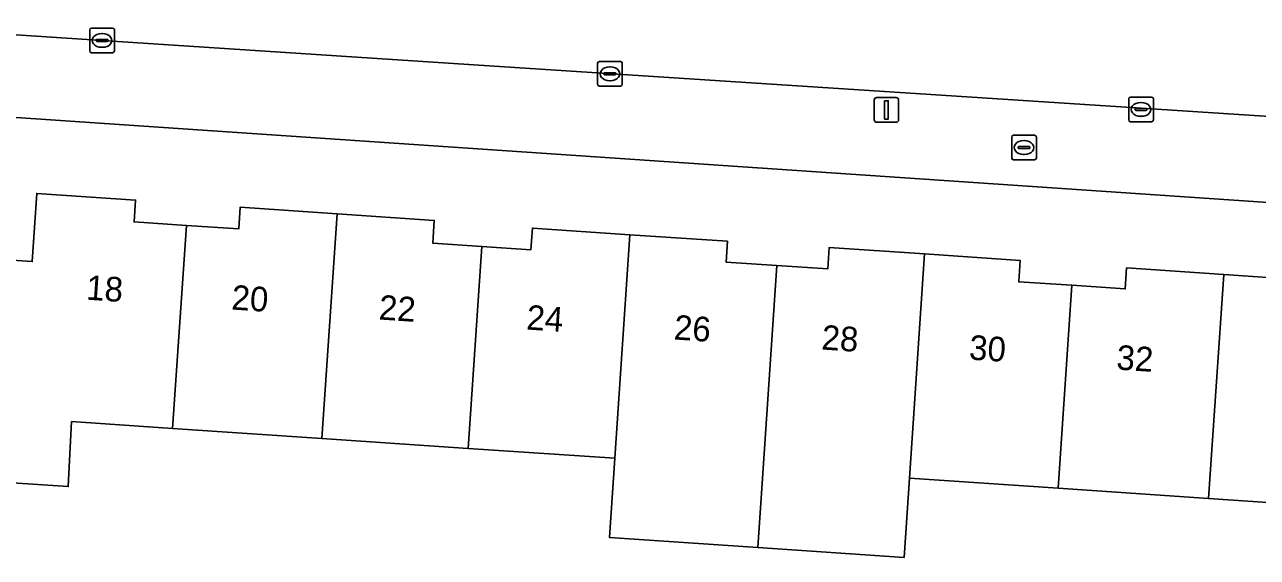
# Model space of a CAD drawing. Extents: x 161848 to 162726, y 385382 to 386521.
# Drawn here: x 162339.2 to 162389.2, y 385439.2 to 385460.8 of the extents above; entities that cross this region are included whole.
import ezdxf

# ---------------------------------------------------------------- set-up
doc = ezdxf.new("R2010")
doc.units = 0
for name, color, linetype in [('IMGEO_Brandkraan', 7, 'Continuous'), ('IMGEO_Erf', 7, 'Continuous'), ('IMGEO_Kolk', 7, 'Continuous'), ('IMGEO_Lichtmast', 7, 'Continuous'), ('IMGEO_Pand', 7, 'Continuous'), ('IMGEO_Pand_nummerreeks', 7, 'Continuous'), ('IMGEO_Rijbaan_lokaal_open', 7, 'Continuous'), ('IMGEO_Voetpad_open', 7, 'Continuous')]:
    doc.layers.add(name, color=color, linetype=linetype)

msp = doc.modelspace()

# ---------------------------------------------------------------- linework, layer by layer
at = {"layer": 'IMGEO_Brandkraan'}
for p, q in [((162379.246, 385455.432), (162379.246, 385456.284)), ((162379.321, 385456.358), (162380.173, 385456.358)), ((162379.734, 385456.138), (162379.759, 385456.138)), ((162380.247, 385456.284), (162380.247, 385455.432)), ((162379.505, 385455.852), (162379.505, 385455.864)), ((162379.943, 385455.815), (162379.545, 385455.815)), ((162379.548, 385455.901), (162379.946, 385455.901)), ((162379.757, 385455.578), (162379.732, 385455.578)), ((162379.989, 385455.864), (162379.989, 385455.852)), ((162380.173, 385455.358), (162379.321, 385455.358))]:
    msp.add_line(p, q, dxfattribs=at)
for points in [[(162379.246, 385455.432), (162379.246, 385456.284)], [(162379.321, 385456.358), (162380.173, 385456.358)], [(162380.247, 385456.284), (162380.247, 385455.432)], [(162380.173, 385455.358), (162379.321, 385455.358)]]:
    msp.add_lwpolyline(points, dxfattribs=at)
for centre, radius, start, end in [((162379.323, 385456.282), 0.0765, 91.552, 178.448), ((162379.323, 385456.282), 0.0765, 91.552, 178.448), ((162380.171, 385456.282), 0.0765, 1.552, 88.448), ((162380.171, 385456.282), 0.0765, 1.552, 88.448), ((162379.545, 385455.861), 0.0403, 85.8775, 175.7526), ((162379.542, 385455.851), 0.0366, 178.938, 274.7102), ((162379.946, 385455.858), 0.043, 264.8664, 352.4533), ((162379.95, 385455.863), 0.0386, 1.7309, 96.639), ((162379.323, 385455.434), 0.0765, 181.552, 268.448), ((162379.323, 385455.434), 0.0765, 181.552, 268.448), ((162380.171, 385455.434), 0.0765, 271.552, 358.448), ((162380.171, 385455.434), 0.0765, 271.552, 358.448)]:
    msp.add_arc(centre, radius, start, end, dxfattribs=at)
for centre, major_axis, ratio, start_param, end_param in [((162379.733, 385455.858), (-0.387, 0.002), 0.722429, 4.712389, 7.853982), ((162379.758, 385455.858), (-0.39, 0.002), 0.717154, 1.570796, 4.712389)]:
    msp.add_ellipse(centre, major_axis=major_axis, ratio=ratio, start_param=start_param, end_param=end_param, dxfattribs=at)
at = {"layer": 'IMGEO_Erf'}
for points in [[(162428.108, 385451.016), (162424.152, 385451.285), (162286.568, 385460.627), (162285.504, 385460.702)], [(162336.992, 385451.392), (162339.469, 385451.225), (162339.657, 385453.996), (162343.668, 385453.725), (162343.608, 385452.839), (162345.731, 385452.695), (162347.854, 385452.552), (162347.913, 385453.433), (162351.854, 385453.167), (162355.796, 385452.9), (162355.734, 385451.978), (162357.73, 385451.843), (162359.725, 385451.708), (162359.785, 385452.588), (162363.745, 385452.32), (162367.703, 385452.053), (162367.646, 385451.21), (162369.71, 385451.07), (162371.773, 385450.931), (162371.831, 385451.798), (162375.71, 385451.536), (162379.59, 385451.274), (162379.532, 385450.412), (162381.692, 385450.266), (162383.856, 385450.119), (162383.913, 385450.971), (162387.858, 385450.704), (162391.799, 385450.438)], [(162393.234, 385441.208), (162387.24, 385441.613), (162381.132, 385442.026), (162375.092, 385442.434), (162374.874, 385439.222), (162368.933, 385439.625), (162362.911, 385440.033), (162363.129, 385443.242), (162357.173, 385443.645), (162351.235, 385444.046), (162345.172, 385444.456), (162341.069, 385444.732), (162340.934, 385442.094), (162336.396, 385442.4)]]:
    msp.add_lwpolyline(points, dxfattribs=at)
at = {"layer": 'IMGEO_Kolk'}
for p, q in [((162341.805, 385459.78), (162341.805, 385460.632)), ((162341.88, 385460.706), (162342.732, 385460.706)), ((162342.293, 385460.486), (162342.318, 385460.486)), ((162342.806, 385460.632), (162342.806, 385459.78)), ((162342.064, 385460.2), (162342.064, 385460.212)), ((162342.502, 385460.163), (162342.104, 385460.163)), ((162342.107, 385460.249), (162342.505, 385460.249)), ((162342.548, 385460.212), (162342.548, 385460.2)), ((162342.732, 385459.706), (162341.88, 385459.706)), ((162342.316, 385459.926), (162342.291, 385459.926)), ((162362.43, 385458.424), (162362.43, 385459.276)), ((162362.505, 385459.35), (162363.357, 385459.35)), ((162362.918, 385459.13), (162362.943, 385459.13)), ((162363.431, 385459.276), (162363.431, 385458.424)), ((162362.689, 385458.844), (162362.689, 385458.856)), ((162363.127, 385458.807), (162362.729, 385458.807)), ((162362.732, 385458.893), (162363.13, 385458.893)), ((162362.941, 385458.57), (162362.916, 385458.57)), ((162363.173, 385458.856), (162363.173, 385458.844)), ((162363.357, 385458.35), (162362.505, 385458.35)), ((162383.997, 385456.978), (162383.997, 385457.83)), ((162384.072, 385457.904), (162384.924, 385457.904)), ((162384.485, 385457.684), (162384.51, 385457.684)), ((162384.998, 385457.83), (162384.998, 385456.978)), ((162384.256, 385457.398), (162384.256, 385457.41)), ((162384.694, 385457.361), (162384.296, 385457.361)), ((162384.299, 385457.447), (162384.697, 385457.447)), ((162384.508, 385457.124), (162384.483, 385457.124)), ((162384.74, 385457.41), (162384.74, 385457.398)), ((162384.924, 385456.904), (162384.072, 385456.904))]:
    msp.add_line(p, q, dxfattribs=at)
for points in [[(162341.805, 385459.78), (162341.805, 385460.632)], [(162341.88, 385460.706), (162342.732, 385460.706)], [(162342.806, 385460.632), (162342.806, 385459.78)], [(162342.732, 385459.706), (162341.88, 385459.706)], [(162362.43, 385458.424), (162362.43, 385459.276)], [(162362.505, 385459.35), (162363.357, 385459.35)], [(162363.431, 385459.276), (162363.431, 385458.424)], [(162363.357, 385458.35), (162362.505, 385458.35)], [(162383.997, 385456.978), (162383.997, 385457.83)], [(162384.072, 385457.904), (162384.924, 385457.904)], [(162384.998, 385457.83), (162384.998, 385456.978)], [(162384.924, 385456.904), (162384.072, 385456.904)]]:
    msp.add_lwpolyline(points, dxfattribs=at)
for centre, radius, start, end in [((162341.882, 385460.63), 0.0765, 91.552, 178.448), ((162341.882, 385460.63), 0.0765, 91.552, 178.448), ((162342.73, 385460.63), 0.0765, 1.552, 88.448), ((162342.73, 385460.63), 0.0765, 1.552, 88.448), ((162342.104, 385460.209), 0.0403, 85.8775, 175.7526), ((162342.101, 385460.199), 0.0366, 178.938, 274.7102), ((162342.505, 385460.206), 0.043, 264.8664, 352.4533), ((162342.509, 385460.211), 0.0386, 1.7309, 96.639), ((162341.882, 385459.782), 0.0765, 181.552, 268.448), ((162341.882, 385459.782), 0.0765, 181.552, 268.448), ((162342.73, 385459.782), 0.0765, 271.552, 358.448), ((162342.73, 385459.782), 0.0765, 271.552, 358.448), ((162362.507, 385459.274), 0.0765, 91.552, 178.448), ((162362.507, 385459.274), 0.0765, 91.552, 178.448), ((162363.355, 385459.274), 0.0765, 1.552, 88.448), ((162363.355, 385459.274), 0.0765, 1.552, 88.448), ((162362.729, 385458.853), 0.0403, 85.8775, 175.7526), ((162362.726, 385458.843), 0.0366, 178.938, 274.7102), ((162363.13, 385458.85), 0.043, 264.8664, 352.4533), ((162363.134, 385458.855), 0.0386, 1.7309, 96.639), ((162362.507, 385458.426), 0.0765, 181.552, 268.448), ((162362.507, 385458.426), 0.0765, 181.552, 268.448), ((162363.355, 385458.426), 0.0765, 271.552, 358.448), ((162363.355, 385458.426), 0.0765, 271.552, 358.448), ((162384.074, 385457.828), 0.0765, 91.552, 178.448), ((162384.074, 385457.828), 0.0765, 91.552, 178.448), ((162384.922, 385457.828), 0.0765, 1.552, 88.448), ((162384.922, 385457.828), 0.0765, 1.552, 88.448), ((162384.074, 385456.98), 0.0765, 181.552, 268.448), ((162384.074, 385456.98), 0.0765, 181.552, 268.448), ((162384.296, 385457.407), 0.0403, 85.8775, 175.7526), ((162384.293, 385457.397), 0.0366, 178.938, 274.7102), ((162384.697, 385457.404), 0.043, 264.8664, 352.4533), ((162384.701, 385457.409), 0.0386, 1.7309, 96.639), ((162384.922, 385456.98), 0.0765, 271.552, 358.448), ((162384.922, 385456.98), 0.0765, 271.552, 358.448)]:
    msp.add_arc(centre, radius, start, end, dxfattribs=at)
for centre, major_axis, ratio, start_param, end_param in [((162342.292, 385460.206), (-0.387, 0.002), 0.722429, 4.712389, 7.853982), ((162342.317, 385460.206), (-0.39, 0.002), 0.717154, 1.570796, 4.712389), ((162362.917, 385458.85), (-0.387, 0.002), 0.722429, 4.712389, 7.853982), ((162362.942, 385458.85), (-0.39, 0.002), 0.717154, 1.570796, 4.712389), ((162384.484, 385457.404), (-0.387, 0.002), 0.722429, 4.712389, 7.853982), ((162384.509, 385457.404), (-0.39, 0.002), 0.717154, 1.570796, 4.712389)]:
    msp.add_ellipse(centre, major_axis=major_axis, ratio=ratio, start_param=start_param, end_param=end_param, dxfattribs=at)
at = {"layer": 'IMGEO_Lichtmast'}
for p, q in [((162373.661, 385456.985), (162373.661, 385457.785)), ((162373.661, 385457.785), (162373.661, 385456.985)), ((162373.761, 385457.885), (162374.551, 385457.885)), ((162374.551, 385457.885), (162373.761, 385457.885)), ((162374.651, 385457.785), (162374.651, 385456.985)), ((162374.651, 385456.985), (162374.651, 385457.785)), ((162374.551, 385456.885), (162373.761, 385456.885)), ((162373.761, 385456.885), (162374.551, 385456.885))]:
    msp.add_line(p, q, dxfattribs=at)
msp.add_lwpolyline([(162374.081, 385457.76), (162374.231, 385457.76), (162374.231, 385457.01), (162374.081, 385457.01), (162374.081, 385457.76)], dxfattribs=at)
for centre, start, end in [((162373.761, 385457.785), 90, 180), ((162373.761, 385457.785), 90, 180), ((162374.551, 385457.785), 0, 90), ((162374.551, 385457.785), 360, 90), ((162373.761, 385456.985), 180, 270), ((162373.761, 385456.985), 180, 270), ((162374.551, 385456.985), 270, 0), ((162374.551, 385456.985), 270, 0)]:
    msp.add_arc(centre, 0.1, start, end, dxfattribs=at)
at = {"layer": 'IMGEO_Pand'}
for points in [[(162345.731, 385452.695), (162343.608, 385452.839), (162343.668, 385453.725), (162339.657, 385453.996), (162339.469, 385451.225), (162336.992, 385451.392), (162336.571, 385445.037), (162336.396, 385442.4), (162340.934, 385442.094), (162341.069, 385444.732), (162345.172, 385444.456)], [(162351.854, 385453.167), (162347.913, 385453.433), (162347.854, 385452.552), (162345.731, 385452.695), (162345.172, 385444.456), (162351.235, 385444.046)], [(162351.235, 385444.046), (162357.173, 385443.645), (162357.73, 385451.843), (162355.734, 385451.978), (162355.796, 385452.9), (162351.854, 385453.167)], [(162363.745, 385452.32), (162359.785, 385452.588), (162359.725, 385451.708), (162357.73, 385451.843), (162357.173, 385443.645), (162363.129, 385443.242)], [(162369.71, 385451.07), (162367.646, 385451.21), (162367.703, 385452.053), (162363.745, 385452.32), (162363.129, 385443.242), (162362.911, 385440.033), (162368.933, 385439.625), (162369.151, 385442.835)], [(162375.71, 385451.536), (162371.831, 385451.798), (162371.773, 385450.931), (162369.71, 385451.07), (162369.151, 385442.835), (162368.933, 385439.625), (162374.874, 385439.222), (162375.092, 385442.434)], [(162381.692, 385450.266), (162379.532, 385450.412), (162379.59, 385451.274), (162375.71, 385451.536), (162375.092, 385442.434), (162381.132, 385442.026)], [(162381.132, 385442.026), (162387.24, 385441.613), (162387.858, 385450.704), (162383.913, 385450.971), (162383.856, 385450.119), (162381.692, 385450.266)], [(162393.797, 385449.505), (162391.745, 385449.644), (162391.799, 385450.438), (162387.858, 385450.704), (162387.24, 385441.613), (162393.234, 385441.208)]]:
    msp.add_lwpolyline(points, close=True, dxfattribs=at)
at = {"layer": 'IMGEO_Rijbaan_lokaal_open'}
msp.add_lwpolyline([(162285.815, 385464.092), (162334.512, 385460.716), (162340.453, 385460.328), (162358.028, 385459.18), (162427.882, 385454.643)], dxfattribs=at)
at = {"layer": 'IMGEO_Voetpad_open'}
for points in [[(162427.882, 385454.643), (162358.028, 385459.18), (162340.453, 385460.328), (162334.512, 385460.716), (162285.815, 385464.092)], [(162285.504, 385460.702), (162286.568, 385460.627), (162424.152, 385451.285), (162428.108, 385451.016)]]:
    msp.add_lwpolyline(points, dxfattribs=at)

# ---------------------------------------------------------------- texts
at = {"layer": 'IMGEO_Pand_nummerreeks'}
for s, rotation, p in [('18', 356.1211, (162341.64, 385449.685)), ('20', 356.1224, (162347.54, 385449.284)), ('22', 356.1224, (162353.524, 385448.879)), ('24', 356.1224, (162359.518, 385448.473)), ('26', 356.1211, (162365.508, 385448.068)), ('28', 356.1211, (162371.502, 385447.661)), ('30', 356.1224, (162377.493, 385447.254)), ('32', 356.1224, (162383.477, 385446.849))]:
    msp.add_text(s, height=1, rotation=rotation, dxfattribs=at).set_placement(p)

doc.saveas('drawing.dxf')
